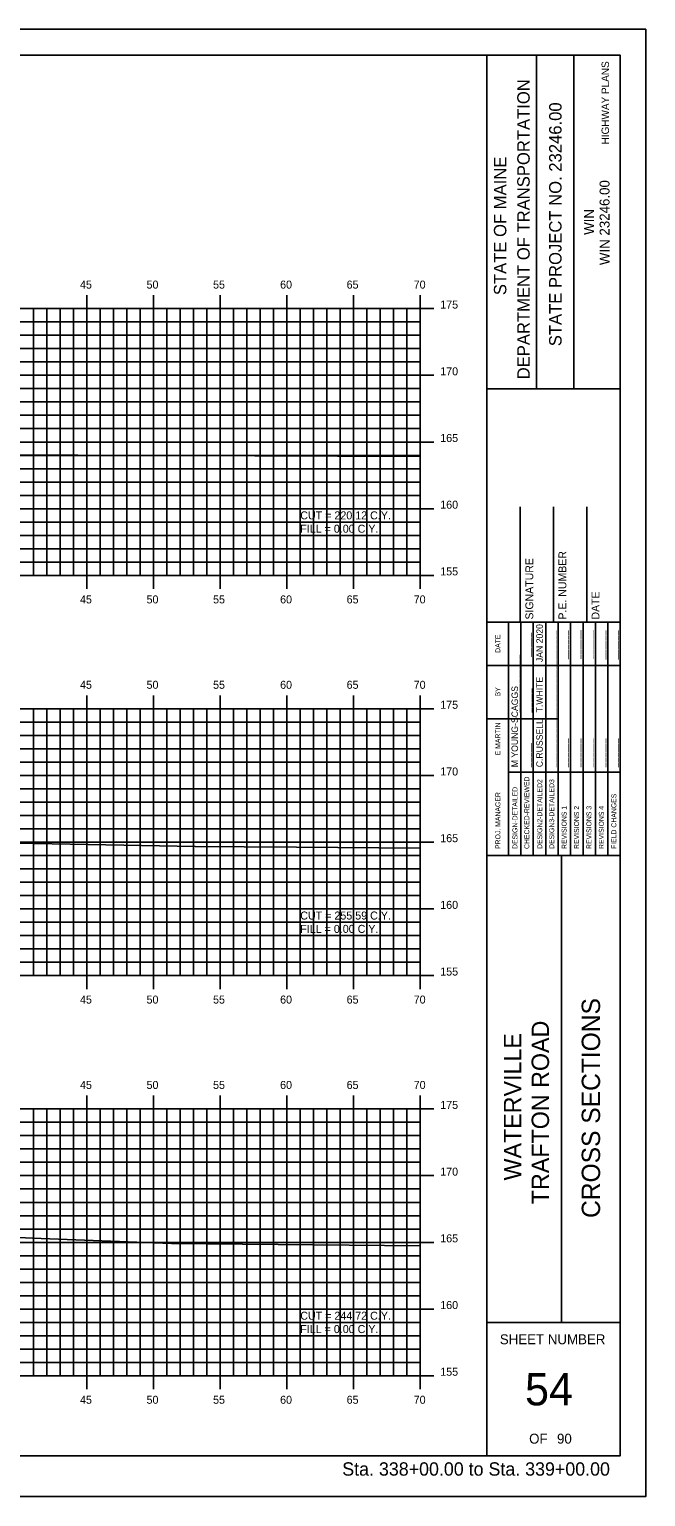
# Model space of a CAD drawing. Extents: x 1142533 to 1142703, y 608981 to 609091.
# Drawn here: x 1142656.7 to 1142703, y 608981.3 to 609091.3 of the extents above; entities that cross this region are included whole.
import ezdxf

# ---------------------------------------------------------------- set-up
doc = ezdxf.new("R2010")
doc.units = 0
for name, color, linetype in [('BORDER', 7, 'Continuous'), ('D_Text_Standard', 7, 'Continuous'), ('H_V ANNOTATION', 7, 'Continuous'), ('HIGHWAY_TITLE', 7, 'Continuous'), ('MAJOR', 7, 'Continuous'), ('MINOR', 7, 'Continuous'), ('PLOT BOUNDARY', 7, 'Continuous'), ('S_Roadway_Centerline', 7, 'Continuous')]:
    doc.layers.add(name, color=color, linetype=linetype)

msp = doc.modelspace()

# ---------------------------------------------------------------- linework, layer by layer
at = {"layer": 'BORDER'}
for p, q in [((1142691.05, 608984.34), (1142691.05, 609089.34)), ((1142694.78, 609064.33), (1142694.78, 609089.33)), ((1142697.58, 609064.33), (1142697.58, 609089.33)), ((1142691.05, 609064.33), (1142701.05, 609064.33)), ((1142693.55, 609046.84), (1142693.55, 609055.49)), ((1142696.05, 609046.84), (1142696.05, 609055.49)), ((1142698.55, 609046.84), (1142698.55, 609055.49)), ((1142691.05, 609046.84), (1142701.05, 609046.84)), ((1142691.05, 609029.34), (1142701.05, 609029.34)), ((1142696.64, 608994.34), (1142696.64, 609029.34)), ((1142691.05, 608994.34), (1142701.05, 608994.34))]:
    msp.add_line(p, q, dxfattribs=at)
msp.add_lwpolyline([(1142541.05, 608984.34), (1142701.05, 608984.34), (1142701.05, 609089.34), (1142541.05, 609089.34)], close=True, dxfattribs=at)
for points in [[(1142692.67, 609043.59), (1142692.67, 609046.84)], [(1142692.67, 609029.34), (1142692.67, 609046.13)], [(1142693.6, 609029.34), (1142693.6, 609046.84)], [(1142694.53, 609046.84), (1142694.53, 609029.34)], [(1142695.46, 609029.34), (1142695.46, 609046.84)], [(1142696.4, 609029.34), (1142696.4, 609046.84)], [(1142697.33, 609029.34), (1142697.33, 609046.84)], [(1142698.26, 609029.34), (1142698.26, 609046.84)], [(1142699.19, 609029.34), (1142699.19, 609046.84)], [(1142700.12, 609029.34), (1142700.12, 609046.84)], [(1142691.05, 609043.59), (1142701.05, 609043.59)], [(1142691.05, 609039.59), (1142692.67, 609039.59)], [(1142692.67, 609039.59), (1142696.4, 609039.59)], [(1142692.67, 609035.59), (1142701.05, 609035.59)]]:
    msp.add_lwpolyline(points, dxfattribs=at)
at = {"layer": 'MAJOR'}
for p, q in [((1142661.05, 609071.34), (1142661.05, 609070.34)), ((1142666.05, 609071.34), (1142666.05, 609070.34)), ((1142671.05, 609071.34), (1142671.05, 609070.34)), ((1142676.05, 609071.34), (1142676.05, 609070.34)), ((1142681.05, 609071.34), (1142681.05, 609070.34)), ((1142686.05, 609071.34), (1142686.05, 609070.34)), ((1142546.05, 609070.34), (1142686.05, 609070.34)), ((1142546.05, 609070.34), (1142686.05, 609070.34)), ((1142661.05, 609050.34), (1142661.05, 609070.34)), ((1142666.05, 609050.34), (1142666.05, 609070.34)), ((1142671.05, 609050.34), (1142671.05, 609070.34)), ((1142676.05, 609050.34), (1142676.05, 609070.34)), ((1142681.05, 609050.34), (1142681.05, 609070.34)), ((1142687.06, 609070.34), (1142685.05, 609070.34)), ((1142686.05, 609050.34), (1142686.05, 609070.34)), ((1142686.05, 609050.34), (1142686.05, 609070.34)), ((1142546.05, 609065.34), (1142686.05, 609065.34)), ((1142687.06, 609065.34), (1142685.05, 609065.34)), ((1142546.05, 609060.34), (1142686.05, 609060.34)), ((1142687.06, 609060.34), (1142685.05, 609060.34)), ((1142546.05, 609055.34), (1142686.05, 609055.34)), ((1142687.06, 609055.34), (1142685.05, 609055.34)), ((1142546.05, 609050.34), (1142686.05, 609050.34)), ((1142546.05, 609050.34), (1142686.05, 609050.34)), ((1142661.05, 609049.33), (1142661.05, 609050.34)), ((1142666.05, 609049.33), (1142666.05, 609050.34)), ((1142671.05, 609049.33), (1142671.05, 609050.34)), ((1142676.05, 609049.33), (1142676.05, 609050.34)), ((1142681.05, 609049.33), (1142681.05, 609050.34)), ((1142687.06, 609050.34), (1142685.05, 609050.34)), ((1142686.05, 609049.33), (1142686.05, 609050.34)), ((1142546.05, 609040.34), (1142686.05, 609040.34)), ((1142546.05, 609040.34), (1142686.05, 609040.34)), ((1142661.05, 609041.34), (1142661.05, 609040.34)), ((1142661.05, 609020.34), (1142661.05, 609040.34)), ((1142666.05, 609041.34), (1142666.05, 609040.34)), ((1142666.05, 609020.34), (1142666.05, 609040.34)), ((1142671.05, 609041.34), (1142671.05, 609040.34)), ((1142671.05, 609020.34), (1142671.05, 609040.34)), ((1142676.05, 609041.34), (1142676.05, 609040.34)), ((1142676.05, 609020.34), (1142676.05, 609040.34)), ((1142681.05, 609041.34), (1142681.05, 609040.34)), ((1142681.05, 609020.34), (1142681.05, 609040.34)), ((1142687.06, 609040.34), (1142685.05, 609040.34)), ((1142686.05, 609041.34), (1142686.05, 609040.34)), ((1142686.05, 609020.34), (1142686.05, 609040.34)), ((1142686.05, 609020.34), (1142686.05, 609040.34)), ((1142546.05, 609035.34), (1142686.05, 609035.34)), ((1142687.06, 609035.34), (1142685.05, 609035.34)), ((1142546.05, 609030.34), (1142686.05, 609030.34)), ((1142687.06, 609030.34), (1142685.05, 609030.34)), ((1142546.05, 609025.34), (1142686.05, 609025.34)), ((1142687.06, 609025.34), (1142685.05, 609025.34)), ((1142546.05, 609020.34), (1142686.05, 609020.34)), ((1142546.05, 609020.34), (1142686.05, 609020.34)), ((1142661.05, 609019.33), (1142661.05, 609020.34)), ((1142666.05, 609019.33), (1142666.05, 609020.34)), ((1142671.05, 609019.33), (1142671.05, 609020.34)), ((1142676.05, 609019.33), (1142676.05, 609020.34)), ((1142681.05, 609019.33), (1142681.05, 609020.34)), ((1142687.06, 609020.34), (1142685.05, 609020.34)), ((1142686.05, 609019.33), (1142686.05, 609020.34)), ((1142661.05, 609011.34), (1142661.05, 609010.34)), ((1142666.05, 609011.34), (1142666.05, 609010.34)), ((1142671.05, 609011.34), (1142671.05, 609010.34)), ((1142676.05, 609011.34), (1142676.05, 609010.34)), ((1142681.05, 609011.34), (1142681.05, 609010.34)), ((1142686.05, 609011.34), (1142686.05, 609010.34)), ((1142546.05, 609010.34), (1142686.05, 609010.34)), ((1142546.05, 609010.34), (1142686.05, 609010.34)), ((1142661.05, 608990.34), (1142661.05, 609010.34)), ((1142666.05, 608990.34), (1142666.05, 609010.34)), ((1142671.05, 608990.34), (1142671.05, 609010.34)), ((1142676.05, 608990.34), (1142676.05, 609010.34)), ((1142681.05, 608990.34), (1142681.05, 609010.34)), ((1142687.06, 609010.34), (1142685.05, 609010.34)), ((1142686.05, 608990.34), (1142686.05, 609010.34)), ((1142686.05, 608990.34), (1142686.05, 609010.34)), ((1142546.05, 609005.34), (1142686.05, 609005.34)), ((1142687.06, 609005.34), (1142685.05, 609005.34)), ((1142546.05, 609000.34), (1142686.05, 609000.34)), ((1142687.06, 609000.34), (1142685.05, 609000.34)), ((1142546.05, 608995.34), (1142686.05, 608995.34)), ((1142687.06, 608995.34), (1142685.05, 608995.34)), ((1142546.05, 608990.34), (1142686.05, 608990.34)), ((1142546.05, 608990.34), (1142686.05, 608990.34)), ((1142661.05, 608989.33), (1142661.05, 608990.34)), ((1142666.05, 608989.33), (1142666.05, 608990.34)), ((1142671.05, 608989.33), (1142671.05, 608990.34)), ((1142676.05, 608989.33), (1142676.05, 608990.34)), ((1142681.05, 608989.33), (1142681.05, 608990.34)), ((1142687.06, 608990.34), (1142685.05, 608990.34)), ((1142686.05, 608989.33), (1142686.05, 608990.34))]:
    msp.add_line(p, q, dxfattribs=at)
at = {"layer": 'MINOR'}
for p, q in [((1142657.05, 609050.34), (1142657.05, 609070.34)), ((1142658.05, 609050.34), (1142658.05, 609070.34)), ((1142659.05, 609050.34), (1142659.05, 609070.34)), ((1142660.05, 609050.34), (1142660.05, 609070.34)), ((1142662.05, 609050.34), (1142662.05, 609070.34)), ((1142663.05, 609050.34), (1142663.05, 609070.34)), ((1142664.05, 609050.34), (1142664.05, 609070.34)), ((1142665.05, 609050.34), (1142665.05, 609070.34)), ((1142667.05, 609050.34), (1142667.05, 609070.34)), ((1142668.05, 609050.34), (1142668.05, 609070.34)), ((1142669.05, 609050.34), (1142669.05, 609070.34)), ((1142670.05, 609050.34), (1142670.05, 609070.34)), ((1142672.05, 609050.34), (1142672.05, 609070.34)), ((1142673.05, 609050.34), (1142673.05, 609070.34)), ((1142674.05, 609050.34), (1142674.05, 609070.34)), ((1142675.05, 609050.34), (1142675.05, 609070.34)), ((1142677.05, 609050.34), (1142677.05, 609070.34)), ((1142678.05, 609050.34), (1142678.05, 609070.34)), ((1142679.05, 609050.34), (1142679.05, 609070.34)), ((1142680.05, 609050.34), (1142680.05, 609070.34)), ((1142682.05, 609050.34), (1142682.05, 609070.34)), ((1142683.05, 609050.34), (1142683.05, 609070.34)), ((1142684.05, 609050.34), (1142684.05, 609070.34)), ((1142685.05, 609050.34), (1142685.05, 609070.34)), ((1142546.05, 609069.34), (1142686.05, 609069.34)), ((1142686.05, 609069.34), (1142685.05, 609069.34)), ((1142546.05, 609068.34), (1142686.05, 609068.34)), ((1142686.05, 609068.34), (1142685.05, 609068.34)), ((1142546.05, 609067.34), (1142686.05, 609067.34)), ((1142686.05, 609067.34), (1142685.05, 609067.34)), ((1142546.05, 609066.34), (1142686.05, 609066.34)), ((1142686.05, 609066.34), (1142685.05, 609066.34)), ((1142546.05, 609064.34), (1142686.05, 609064.34)), ((1142686.05, 609064.34), (1142685.05, 609064.34)), ((1142546.05, 609063.34), (1142686.05, 609063.34)), ((1142546.05, 609062.34), (1142686.05, 609062.34)), ((1142686.05, 609063.34), (1142685.05, 609063.34)), ((1142686.05, 609062.34), (1142685.05, 609062.34)), ((1142546.05, 609061.34), (1142686.05, 609061.34)), ((1142686.05, 609061.34), (1142685.05, 609061.34)), ((1142546.05, 609059.34), (1142686.05, 609059.34)), ((1142686.05, 609059.34), (1142685.05, 609059.34)), ((1142546.05, 609058.34), (1142686.05, 609058.34)), ((1142686.05, 609058.34), (1142685.05, 609058.34)), ((1142546.05, 609057.34), (1142686.05, 609057.34)), ((1142686.05, 609057.34), (1142685.05, 609057.34)), ((1142546.05, 609056.34), (1142686.05, 609056.34)), ((1142686.05, 609056.34), (1142685.05, 609056.34)), ((1142546.05, 609054.34), (1142686.05, 609054.34)), ((1142686.05, 609054.34), (1142685.05, 609054.34)), ((1142546.05, 609053.34), (1142686.05, 609053.34)), ((1142686.05, 609053.34), (1142685.05, 609053.34)), ((1142546.05, 609052.34), (1142686.05, 609052.34)), ((1142546.05, 609051.34), (1142686.05, 609051.34)), ((1142686.05, 609052.34), (1142685.05, 609052.34)), ((1142686.05, 609051.34), (1142685.05, 609051.34)), ((1142657.05, 609020.34), (1142657.05, 609040.34)), ((1142658.05, 609020.34), (1142658.05, 609040.34)), ((1142659.05, 609020.34), (1142659.05, 609040.34)), ((1142660.05, 609020.34), (1142660.05, 609040.34)), ((1142662.05, 609020.34), (1142662.05, 609040.34)), ((1142663.05, 609020.34), (1142663.05, 609040.34)), ((1142664.05, 609020.34), (1142664.05, 609040.34)), ((1142665.05, 609020.34), (1142665.05, 609040.34)), ((1142667.05, 609020.34), (1142667.05, 609040.34)), ((1142668.05, 609020.34), (1142668.05, 609040.34)), ((1142669.05, 609020.34), (1142669.05, 609040.34)), ((1142670.05, 609020.34), (1142670.05, 609040.34)), ((1142672.05, 609020.34), (1142672.05, 609040.34)), ((1142673.05, 609020.34), (1142673.05, 609040.34)), ((1142674.05, 609020.34), (1142674.05, 609040.34)), ((1142675.05, 609020.34), (1142675.05, 609040.34)), ((1142677.05, 609020.34), (1142677.05, 609040.34)), ((1142678.05, 609020.34), (1142678.05, 609040.34)), ((1142679.05, 609020.34), (1142679.05, 609040.34)), ((1142680.05, 609020.34), (1142680.05, 609040.34)), ((1142682.05, 609020.34), (1142682.05, 609040.34)), ((1142683.05, 609020.34), (1142683.05, 609040.34)), ((1142684.05, 609020.34), (1142684.05, 609040.34)), ((1142685.05, 609020.34), (1142685.05, 609040.34)), ((1142546.05, 609039.34), (1142686.05, 609039.34)), ((1142686.05, 609039.34), (1142685.05, 609039.34)), ((1142546.05, 609038.34), (1142686.05, 609038.34)), ((1142686.05, 609038.34), (1142685.05, 609038.34)), ((1142546.05, 609037.34), (1142686.05, 609037.34)), ((1142686.05, 609037.34), (1142685.05, 609037.34)), ((1142546.05, 609036.34), (1142686.05, 609036.34)), ((1142686.05, 609036.34), (1142685.05, 609036.34)), ((1142546.05, 609034.34), (1142686.05, 609034.34)), ((1142686.05, 609034.34), (1142685.05, 609034.34)), ((1142546.05, 609033.34), (1142686.05, 609033.34)), ((1142686.05, 609033.34), (1142685.05, 609033.34)), ((1142546.05, 609032.34), (1142686.05, 609032.34)), ((1142686.05, 609032.34), (1142685.05, 609032.34)), ((1142546.05, 609031.34), (1142686.05, 609031.34)), ((1142686.05, 609031.34), (1142685.05, 609031.34)), ((1142546.05, 609029.34), (1142686.05, 609029.34)), ((1142686.05, 609029.34), (1142685.05, 609029.34)), ((1142546.05, 609028.34), (1142686.05, 609028.34)), ((1142686.05, 609028.34), (1142685.05, 609028.34)), ((1142546.05, 609027.34), (1142686.05, 609027.34)), ((1142686.05, 609027.34), (1142685.05, 609027.34)), ((1142546.05, 609026.34), (1142686.05, 609026.34)), ((1142686.05, 609026.34), (1142685.05, 609026.34)), ((1142546.05, 609024.34), (1142686.05, 609024.34)), ((1142686.05, 609024.34), (1142685.05, 609024.34)), ((1142546.05, 609023.34), (1142686.05, 609023.34)), ((1142686.05, 609023.34), (1142685.05, 609023.34)), ((1142546.05, 609022.34), (1142686.05, 609022.34)), ((1142686.05, 609022.34), (1142685.05, 609022.34)), ((1142546.05, 609021.34), (1142686.05, 609021.34)), ((1142686.05, 609021.34), (1142685.05, 609021.34)), ((1142657.05, 608990.34), (1142657.05, 609010.34)), ((1142658.05, 608990.34), (1142658.05, 609010.34)), ((1142659.05, 608990.34), (1142659.05, 609010.34)), ((1142660.05, 608990.34), (1142660.05, 609010.34)), ((1142662.05, 608990.34), (1142662.05, 609010.34)), ((1142663.05, 608990.34), (1142663.05, 609010.34)), ((1142664.05, 608990.34), (1142664.05, 609010.34)), ((1142665.05, 608990.34), (1142665.05, 609010.34)), ((1142667.05, 608990.34), (1142667.05, 609010.34)), ((1142668.05, 608990.34), (1142668.05, 609010.34)), ((1142669.05, 608990.34), (1142669.05, 609010.34)), ((1142670.05, 608990.34), (1142670.05, 609010.34)), ((1142672.05, 608990.34), (1142672.05, 609010.34)), ((1142673.05, 608990.34), (1142673.05, 609010.34)), ((1142674.05, 608990.34), (1142674.05, 609010.34)), ((1142675.05, 608990.34), (1142675.05, 609010.34)), ((1142677.05, 608990.34), (1142677.05, 609010.34)), ((1142678.05, 608990.34), (1142678.05, 609010.34)), ((1142679.05, 608990.34), (1142679.05, 609010.34)), ((1142680.05, 608990.34), (1142680.05, 609010.34)), ((1142682.05, 608990.34), (1142682.05, 609010.34)), ((1142683.05, 608990.34), (1142683.05, 609010.34)), ((1142684.05, 608990.34), (1142684.05, 609010.34)), ((1142685.05, 608990.34), (1142685.05, 609010.34)), ((1142546.05, 609009.34), (1142686.05, 609009.34)), ((1142686.05, 609009.34), (1142685.05, 609009.34)), ((1142546.05, 609008.34), (1142686.05, 609008.34)), ((1142546.05, 609007.34), (1142686.05, 609007.34)), ((1142686.05, 609008.34), (1142685.05, 609008.34)), ((1142686.05, 609007.34), (1142685.05, 609007.34)), ((1142546.05, 609006.34), (1142686.05, 609006.34)), ((1142686.05, 609006.34), (1142685.05, 609006.34)), ((1142546.05, 609004.34), (1142686.05, 609004.34)), ((1142686.05, 609004.34), (1142685.05, 609004.34)), ((1142546.05, 609003.34), (1142686.05, 609003.34)), ((1142686.05, 609003.34), (1142685.05, 609003.34)), ((1142546.05, 609002.34), (1142686.05, 609002.34)), ((1142686.05, 609002.34), (1142685.05, 609002.34)), ((1142546.05, 609001.34), (1142686.05, 609001.34)), ((1142686.05, 609001.34), (1142685.05, 609001.34)), ((1142546.05, 608999.34), (1142686.05, 608999.34)), ((1142686.05, 608999.34), (1142685.05, 608999.34)), ((1142546.05, 608998.34), (1142686.05, 608998.34)), ((1142686.05, 608998.34), (1142685.05, 608998.34)), ((1142546.05, 608997.34), (1142686.05, 608997.34)), ((1142546.05, 608996.34), (1142686.05, 608996.34)), ((1142686.05, 608997.34), (1142685.05, 608997.34)), ((1142686.05, 608996.34), (1142685.05, 608996.34)), ((1142546.05, 608994.34), (1142686.05, 608994.34)), ((1142686.05, 608994.34), (1142685.05, 608994.34)), ((1142546.05, 608993.34), (1142686.05, 608993.34)), ((1142686.05, 608993.34), (1142685.05, 608993.34)), ((1142546.05, 608992.34), (1142686.05, 608992.34)), ((1142686.05, 608992.34), (1142685.05, 608992.34)), ((1142546.05, 608991.34), (1142686.05, 608991.34)), ((1142686.05, 608991.34), (1142685.05, 608991.34))]:
    msp.add_line(p, q, dxfattribs=at)
at = {"layer": 'PLOT BOUNDARY'}
msp.add_lwpolyline([(1142532.96, 608981.28), (1142702.96, 608981.28), (1142702.96, 609091.28), (1142532.96, 609091.28)], close=True, dxfattribs=at)
at = {"layer": 'S_Roadway_Centerline'}
for points in [[(1142546.05, 609060.6), (1142564.14, 609060.41), (1142571.11, 609060.44), (1142586.02, 609060.07), (1142589.15, 609060.03), (1142594.06, 609059.73), (1142596.74, 609059.79), (1142597.58, 609059.79), (1142598.9, 609060.23), (1142602.89, 609060.22), (1142602.89, 609060.22), (1142602.93, 609060.22), (1142613.82, 609060.42), (1142618.98, 609060.24), (1142625.02, 609060.11), (1142626.44, 609059.99), (1142628.87, 609059.71), (1142630.6, 609059.31), (1142631.85, 609058.88), (1142634.66, 609059.3), (1142636.46, 609059.59), (1142653.28, 609059.37), (1142667.44, 609059.33), (1142686.05, 609059.25)], [(1142546.05, 609031.58), (1142570.41, 609031.27), (1142587.09, 609030.8), (1142590.29, 609030.81), (1142591.49, 609030.6), (1142594.78, 609029.67), (1142598.5, 609030.52), (1142599.06, 609030.65), (1142599.41, 609030.68), (1142602.14, 609030.78), (1142607.39, 609030.89), (1142613.31, 609031.06), (1142619, 609030.94), (1142624.67, 609030.75), (1142626.89, 609030.37), (1142628.42, 609030.24), (1142631.94, 609029.67), (1142633.79, 609029.25), (1142635.7, 609029.56), (1142638.33, 609030.59), (1142669.17, 609030.02), (1142672.84, 609029.98), (1142676.77, 609029.96), (1142686.05, 609029.89)], [(1142546.05, 609001.21), (1142548.7, 609001.19), (1142572, 609000.97), (1142582.29, 609000.94), (1142589.04, 609000.83), (1142592.57, 609000.31), (1142594.49, 609000.01), (1142595.63, 609000.22), (1142597.97, 609000.96), (1142599.53, 609001.08), (1142601.32, 609001.18), (1142605.5, 609001.27), (1142612.23, 609001.45), (1142618.84, 609001.2), (1142623.39, 609001.1), (1142625.79, 609000.67), (1142627.48, 609000.38), (1142629.79, 609000.09), (1142632.43, 608999.67), (1142639.12, 609000.61), (1142641.12, 609001.4), (1142656.97, 609000.66), (1142667.4, 609000.25), (1142686.05, 609000.08)]]:
    msp.add_lwpolyline(points, dxfattribs=at)

# ---------------------------------------------------------------- texts
at = {"layer": 'BORDER'}
for s, height, p in [('DEPARTMENT OF TRANSPORTATION', 0.9318, (1142694.26, 609065.04)), ('STATE PROJECT NO. 23246.00', 0.9318, (1142696.65, 609067.52)), ('STATE OF MAINE', 0.9318, (1142692.51, 609071.35)), ('WIN 23246.00', 0.7453, (1142700.25, 609073.6)), ('WIN', 0.745, (1142699.09, 609075.87)), ('SIGNATURE', 0.591, (1142694.53, 609047.03)), ('P.E. NUMBER', 0.5906, (1142697.01, 609047.03)), ('DATE', 0.591, (1142699.49, 609047.03)), ('DATE', 0.371, (1142692.06, 609044.54)), ('_____', 0.485, (1142694.27, 609044.24)), ('JAN 2020', 0.485, (1142695.24, 609043.84)), ('______', 0.485, (1142696.13, 609044.06)), ('______', 0.485, (1142697.07, 609044.06)), ('______', 0.485, (1142698, 609044.07)), ('______', 0.485, (1142698.93, 609044.07)), ('______', 0.485, (1142699.86, 609044.04)), ('______', 0.485, (1142700.79, 609044.04)), ('____________', 0.4845, (1142693.38, 609040.07)), ('____________', 0.4845, (1142696.13, 609040.07)), ('T.WHITE', 0.485, (1142695.24, 609040.07)), ('BY', 0.371, (1142692.06, 609041.27)), ('M YOUNG-SCAGGS', 0.4845, (1142693.38, 609035.96)), ('_____', 0.485, (1142694.31, 609040.07)), ('C.RUSSELL', 0.485, (1142695.24, 609035.96)), ('____________', 0.4845, (1142696.13, 609035.96)), ('E MARTIN', 0.373, (1142692.06, 609036.85)), ('______', 0.485, (1142697.07, 609035.96)), ('______', 0.485, (1142698, 609035.96)), ('______', 0.485, (1142698.93, 609035.96)), ('______', 0.485, (1142699.86, 609035.96)), ('______', 0.485, (1142700.79, 609035.96)), ('_____', 0.485, (1142694.27, 609035.96)), ('CHECKED-REVIEWED', 0.3727, (1142694.23, 609029.83)), ('DESIGN2-DETAILED2', 0.3727, (1142695.2, 609029.83)), ('DESIGN3-DETAILED3', 0.3727, (1142696.1, 609029.83)), ('PROJ. MANAGER', 0.3727, (1142692.06, 609029.83)), ('DESIGN-DETAILED', 0.3727, (1142693.34, 609029.83)), ('FIELD CHANGES', 0.3727, (1142700.76, 609029.83)), ('REVISIONS 1', 0.3727, (1142697.03, 609029.83)), ('REVISIONS 2', 0.3727, (1142697.96, 609029.83)), ('REVISIONS 3', 0.3727, (1142698.89, 609029.83)), ('REVISIONS 4', 0.3727, (1142699.82, 609029.83)), ('CROSS SECTIONS', 1.3779, (1142699.54, 609002.17))]:
    msp.add_text(s, height=height, rotation=90, dxfattribs=at).set_placement(p)
for s, height, p in [('SHEET NUMBER', 0.7453, (1142692.02, 608992.7)), ('54', 2.419, (1142693.91, 608988.12)), ('OF', 0.745, (1142694.22, 608985.25)), ('90', 0.745, (1142696.31, 608985.25))]:
    msp.add_text(s, height=height, dxfattribs=at).set_placement(p)
at = {"layer": 'D_Text_Standard'}
for s, p in [('CUT = 220.12 C.Y.', (1142677.05, 609054.54)), ('FILL = 0.00 C.Y.', (1142677.05, 609053.54)), ('CUT = 255.59 C.Y.', (1142677.05, 609024.54)), ('FILL = 0.00 C.Y.', (1142677.05, 609023.54)), ('CUT = 244.72 C.Y.', (1142677.05, 608994.54)), ('FILL = 0.00 C.Y.', (1142677.05, 608993.54))]:
    msp.add_text(s, height=0.6, dxfattribs=at).set_placement(p)
at = {"layer": 'H_V ANNOTATION'}
for s, height, p in [('45', 0.6, (1142660.53, 609071.84)), ('50', 0.6, (1142665.52, 609071.84)), ('55', 0.6, (1142670.51, 609071.84)), ('60', 0.6, (1142675.54, 609071.84)), ('65', 0.6, (1142680.53, 609071.84)), ('70', 0.6, (1142685.56, 609071.84)), ('175', 0.6, (1142687.55, 609070.34)), ('170', 0.6, (1142687.55, 609065.34)), ('165', 0.6, (1142687.55, 609060.34)), ('160', 0.6, (1142687.55, 609055.34)), ('155', 0.6, (1142687.55, 609050.34)), ('45', 0.6, (1142660.53, 609048.24)), ('50', 0.6, (1142665.52, 609048.24)), ('55', 0.6, (1142670.51, 609048.24)), ('60', 0.6, (1142675.54, 609048.24)), ('65', 0.6, (1142680.53, 609048.24)), ('70', 0.6, (1142685.56, 609048.24)), ('45', 0.6, (1142660.53, 609041.84)), ('50', 0.6, (1142665.52, 609041.84)), ('55', 0.6, (1142670.51, 609041.84)), ('60', 0.6, (1142675.54, 609041.84)), ('65', 0.6, (1142680.53, 609041.84)), ('70', 0.6, (1142685.56, 609041.84)), ('175', 0.6, (1142687.55, 609040.34)), ('170', 0.6, (1142687.55, 609035.34)), ('165', 0.6, (1142687.55, 609030.34)), ('160', 0.6, (1142687.55, 609025.34)), ('155', 0.6, (1142687.55, 609020.34)), ('45', 0.6, (1142660.53, 609018.24)), ('50', 0.6, (1142665.52, 609018.24)), ('55', 0.6, (1142670.51, 609018.24)), ('60', 0.6, (1142675.54, 609018.24)), ('65', 0.6, (1142680.53, 609018.24)), ('70', 0.6, (1142685.56, 609018.24)), ('45', 0.6, (1142660.53, 609011.84)), ('50', 0.6, (1142665.52, 609011.84)), ('55', 0.6, (1142670.51, 609011.84)), ('60', 0.6, (1142675.54, 609011.84)), ('65', 0.6, (1142680.53, 609011.84)), ('70', 0.6, (1142685.56, 609011.84)), ('175', 0.6, (1142687.55, 609010.34)), ('170', 0.6, (1142687.55, 609005.34)), ('165', 0.6, (1142687.55, 609000.34)), ('160', 0.6, (1142687.55, 608995.34)), ('155', 0.6, (1142687.55, 608990.34)), ('45', 0.6, (1142660.53, 608988.24)), ('50', 0.6, (1142665.52, 608988.24)), ('55', 0.6, (1142670.51, 608988.24)), ('60', 0.6, (1142675.54, 608988.24)), ('65', 0.6, (1142680.53, 608988.24)), ('70', 0.6, (1142685.56, 608988.24)), ('Sta. 338+00.00 to Sta. 339+00.00', 1.0002, (1142680.2, 608982.85))]:
    msp.add_text(s, height=height, dxfattribs=at).set_placement(p)
at = {"layer": 'HIGHWAY_TITLE'}
for s, height, p in [('HIGHWAY PLANS', 0.559, (1142700.21, 609082.65)), ('TRAFTON ROAD', 1.3043, (1142695.71, 609003.2)), ('WATERVILLE', 1.304, (1142693.63, 609004.98))]:
    msp.add_text(s, height=height, rotation=90, dxfattribs=at).set_placement(p)

doc.saveas('drawing.dxf')
